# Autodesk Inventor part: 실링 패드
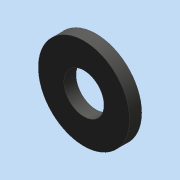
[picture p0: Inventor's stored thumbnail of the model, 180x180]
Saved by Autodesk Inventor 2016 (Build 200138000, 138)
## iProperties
Created: 2024-09
Part Number: 실링 패드
Material: 일반
Document SubType Name: Modeling
Designer: pc-7
Density: 1 g/cm^3
Appearance: 기본값
Author: jhkim
Sending System: Autodesk Inventor 2025
Preprocessor: ST-DEVELOPER v20
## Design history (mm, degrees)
node "실링 패드1"
node "솔리드2"
node "솔리드1"
